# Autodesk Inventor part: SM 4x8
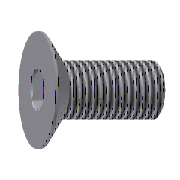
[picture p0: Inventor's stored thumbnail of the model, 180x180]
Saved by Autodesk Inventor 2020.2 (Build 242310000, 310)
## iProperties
Manager: www.cadconsulting.pl
Company: Fabian Stasiak CAD Consulting
Created: 2014-02
Part Number: SM 4x8
Material: Stal, miękka
Description: Socket Head Countersunk Screw
Document SubType Name: Modeling
Designer: F.Stasiak
Standard Revision: 1
Manufacturer: DME
Language: pl-PL
Size Designation: 4x8
Categories: <MemberInstance><Categories><Category DisplayName="Forma wtryskowa" InternalName="349578f2-f4d4-4954-8c09-8e99297a61c0" Mnemonic="MOLD"><Category DisplayName="C
Mass: 0.132503 g
Surface Area: 2.09825 cm^2
Volume: 0.132503 cm^3
Density: 7.85 g/cm^3
Appearance: Częściowo polerowana
Catalog Web Link: www.expertbooks.pl
IsCustomPart: 0
Author: F.Stasiak
Subject: Zbiór ćwiczeń. Autodesk Inventor 2020. Kurs Professional
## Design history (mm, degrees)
sketch "Sketch1"
  geometry: L1 (0, 1.443)-(0, 4); L2 (0, 4)-(0.3, 4); L3 (0.3, 4)-(2.3, 2); L4 (2.3, 2)-(8, 2); L5 (8, 2)-(8, 0); L6 (0.193, 1.25)-(2, 1.25); L7 (2, 1.25)-(2.751, 0); L8 (9.6, 0)-(-1.6, 0) reference; L9 (0.193, 1.25)-(0, 1.443); L10 (2.751, 0)-(8, 0); 1 further point
  constraints: 18 end point, 3 point on line, 2 parallel, 1 horizontal, 1 perpendicular, 1 vertical
  dimensions: "d1" = 8 distance between parallel lines of L5 L1 (= L); "d2" = 2.3 distance from line of L3.end L1 (= k); "d8" = 8 diameter of L2 L8 (= dk); "d9" = 2.5 diameter of L6 L8 (= sw); "d10" = 59 deg angle of L7 L8; "d11" = 45 deg angle of L3 L8 (= 0.5 x A_); "d12" = 4 diameter of L4 L8 (= d); "d14" = 45 deg angle of L8 L9; "d15" = 2 distance from line of L6.end L1 (= t); "d16" = 2.88675 diameter of L1.start L8 (= 1.1547 x sw)
revolve "Revolution1" sketch "Sketch1" stored, may be unused: angle "d39" = 90 deg
sketch "Sketch2"
  geometry: L1 (0, 1.443)-(1.25, 0.722); L2 (1.25, 0.722)-(1.25, -0.722); L3 (1.25, -0.722)-(0, -1.443); L4 (0, -1.443)-(-1.25, -0.722); L5 (-1.25, -0.722)-(-1.25, 0.722); L6 (-1.25, 0.722)-(0, 1.443); 2 further points
  constraints: 12 end point, 2 vertical alignment, 1 coincident, 14 other
extrude "Extrusion1" cut sketch "Sketch2" taper "d3" = 0 deg; stored distance "d40" = 10
thread "Thread1" dims "d4" = 5.7 (= b), "d5" = 0
chamfer "Chamfer1" distance "d17" = 0.35 (= 0.5 x P); stored, may be unused: second distance "d37" = 2, angle "d38" = 45 deg
body "Solid1"
other parameters: "d" = 4 [user parameter; used in 1 equation term], "L" = 8 [user parameter; used in 1 equation term], "b" = 5.7 [user parameter; used in 1 equation term], "dk" = 8 [user parameter; used in 1 equation term], "k" = 2.3 [user parameter; used in 1 equation term], "sw" = 2.5 [user parameter; used in 2 equation terms], "P" = 0.7 [user parameter; used in 1 equation term], "t" = 2 [user parameter; used in 1 equation term], "d7" = 0, "A_" = 90 deg [user parameter; used in 1 equation term], "d41" = 0
